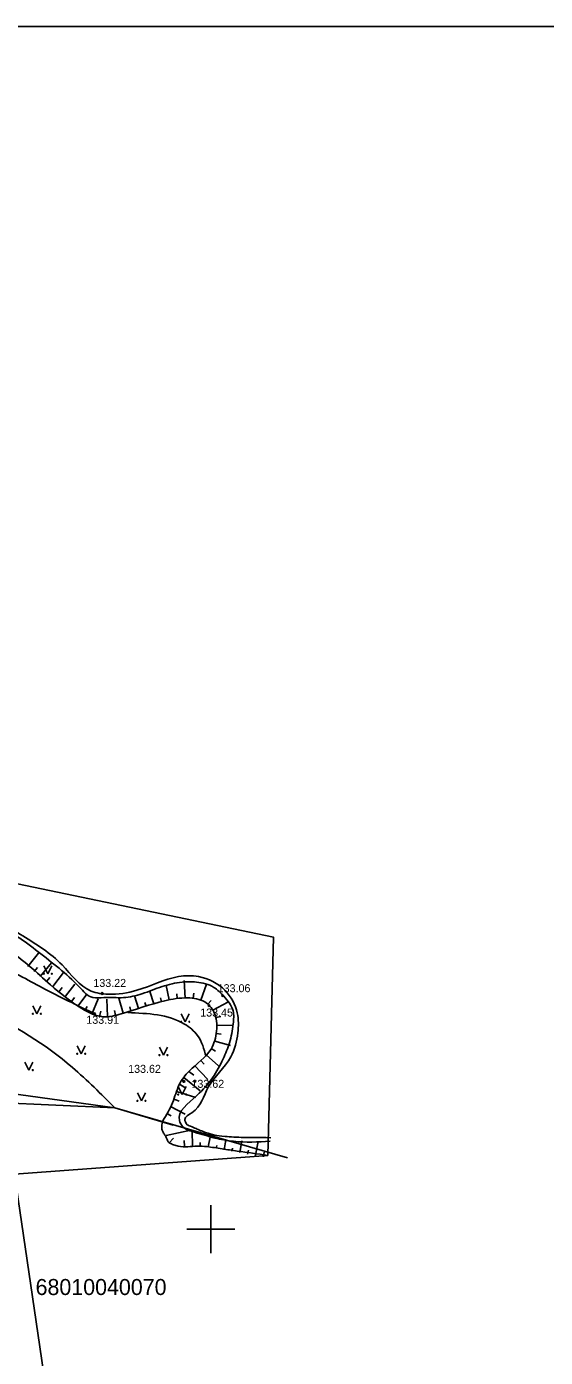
# Model space of a CAD drawing. Extents: x 728710 to 728960, y 272811 to 273475.
# Drawn here: x 728788.5 to 728820.9, y 273392 to 273475.1 of the extents above; entities that cross this region are included whole.
import ezdxf

# ---------------------------------------------------------------- set-up
doc = ezdxf.new("R2010")
doc.units = 0
for name, color, linetype in [('Level 10', 7, 'Continuous'), ('Level 12', 7, 'Continuous'), ('Level 28', 7, 'Continuous'), ('Level 30', 7, 'Continuous'), ('Level 31', 7, 'Continuous'), ('Level 33', 7, 'Continuous'), ('Level 34', 7, 'Continuous'), ('Level 48', 7, 'Continuous'), ('Level 57', 7, 'Continuous'), ('RAMI_PLAN_####_TKST_#', 7, 'Continuous'), ('RAMI_UZMR_####_####_#', 7, 'Continuous'), ('ROBZ_KADS_####_TKST_#', 7, 'Continuous'), ('ROBZ_UZMR_####_####_#', 7, 'Continuous'), ('TERT_KONT_####_####_#', 7, 'Continuous')]:
    doc.layers.add(name, color=color, linetype=linetype)

msp = doc.modelspace()

# ---------------------------------------------------------------- linework, layer by layer
at = {"layer": 'Level 10'}
for p, q in [((728800, 273401.5), (728800, 273400)), ((728798.5, 273400), (728800, 273400)), ((728800, 273400), (728800, 273398.5)), ((728800, 273400), (728801.5, 273400))]:
    msp.add_line(p, q, dxfattribs=at)
at = {"layer": 'Level 12'}
for p, q in [((728788.569, 273416.409), (728789.245, 273417.235)), ((728789.342, 273415.775), (728790.045, 273416.631)), ((728788.956, 273416.092), (728789.163, 273416.345)), ((728789.732, 273415.462), (728789.941, 273415.724)), ((728790.125, 273415.153), (728790.799, 273416.026)), ((728790.521, 273414.847), (728790.712, 273415.095)), ((728790.917, 273414.542), (728791.511, 273415.312)), ((728796.438, 273414.071), (728796.2, 273414.848)), ((728797.405, 273414.324), (728797.213, 273415.221)), ((728798.397, 273414.436), (728798.337, 273415.522)), ((728799.378, 273414.301), (728799.728, 273415.302)), ((728791.316, 273414.241), (728791.482, 273414.462)), ((728791.719, 273413.945), (728792.253, 273414.682)), ((728792.573, 273413.429), (728792.953, 273414.392)), ((728793.549, 273413.276), (728793.494, 273414.365)), ((728794.526, 273413.483), (728794.253, 273414.422)), ((728795.483, 273413.772), (728795.227, 273414.577)), ((728795.96, 273413.923), (728795.887, 273414.154)), ((728796.919, 273414.208), (728796.851, 273414.454)), ((728797.899, 273414.397), (728797.868, 273414.7)), ((728798.896, 273414.427), (728798.944, 273414.746)), ((728799.814, 273414.058), (728800.019, 273414.291)), ((728800.133, 273413.678), (728801.065, 273414.183)), ((728792.132, 273413.663), (728792.285, 273413.905)), ((728793.051, 273413.289), (728793.119, 273413.611)), ((728794.042, 273413.358), (728793.979, 273413.666)), ((728795.006, 273413.622), (728794.931, 273413.883)), ((728800.315, 273413.215), (728800.626, 273413.284)), ((728800.375, 273412.72), (728801.419, 273412.747)), ((728800.241, 273411.732), (728801.221, 273411.461)), ((728800.34, 273412.222), (728800.643, 273412.181)), ((728799.716, 273410.893), (728800.481, 273410.202)), ((728800.031, 273411.28), (728800.285, 273411.119)), ((728798.636, 273409.854), (728798.93, 273409.616)), ((728798.98, 273410.216), (728799.814, 273409.348)), ((728799.353, 273410.55), (728799.575, 273410.299)), ((728798.045, 273409.049), (728798.383, 273408.846)), ((728798.322, 273409.465), (728799.343, 273408.638)), ((728797.858, 273408.587), (728799.071, 273408.215)), ((728797.486, 273407.662), (728798.4, 273407.173)), ((728797.705, 273408.111), (728798.022, 273407.997)), ((728797.014, 273406.78), (728797.023, 273406.775)), ((728797.25, 273407.221), (728797.514, 273407.08)), ((728797.1, 273406.338), (728797.103, 273406.338)), ((728797.206, 273405.849), (728798.749, 273406.184)), ((728797.397, 273405.397), (728797.676, 273405.688)), ((728798.846, 273405.182), (728798.833, 273406.147)), ((728799.842, 273405.138), (728799.951, 273405.733)), ((728797.847, 273405.199), (728797.849, 273405.209)), ((728798.346, 273405.175), (728798.341, 273405.532)), ((728799.345, 273405.188), (728799.343, 273405.412)), ((728800.334, 273405.048), (728800.366, 273405.223)), ((728800.826, 273404.958), (728800.937, 273405.568)), ((728801.317, 273404.868), (728801.354, 273405.066)), ((728801.809, 273404.778), (728801.945, 273405.517)), ((728802.301, 273404.687), (728802.346, 273404.933)), ((728802.793, 273404.598), (728802.955, 273405.498)), ((728803.285, 273404.51), (728803.338, 273404.804))]:
    msp.add_line(p, q, dxfattribs=at)
for points in [[(728769.216, 273417.292), (728772.241, 273417.34), (728773.448, 273417.819), (728775.383, 273417.819), (728777.318, 273417.819), (728779.801, 273417.819), (728783.205, 273418.186), (728785.14, 273418.186), (728787.244, 273417.459), (728789.982, 273415.263), (728791.949, 273413.779), (728793.31, 273413.264), (728794.399, 273413.446), (728797.122, 273414.264), (728798.559, 273414.445), (728799.618, 273414.188), (728800.193, 273413.567), (728800.36, 273412.37), (728800.012, 273411.25), (728798.652, 273409.873), (728798.03, 273409.023), (728797.606, 273407.887), (728797.007, 273406.767)], [(728803.558, 273404.599), (728801.654, 273404.877), (728800.701, 273405.011), (728799.751, 273405.154), (728799.159, 273405.179), (728798.561, 273405.148), (728797.968, 273405.18), (728797.679, 273405.258), (728797.537, 273405.319), (728797.467, 273405.356), (728797.397, 273405.397), (728797.299, 273405.526), (728797.242, 273405.681), (728797.138, 273405.865), (728797.025, 273406.047), (728796.944, 273406.233), (728796.936, 273406.425), (728797.007, 273406.767)]]:
    msp.add_spline(points, degree=3, dxfattribs=at)
at = {"layer": 'Level 28'}
for p, q in [((728786.214, 273408.662), (728794.012, 273407.568)), ((728794.012, 273407.568), (728797.649, 273406.5))]:
    msp.add_line(p, q, dxfattribs=at)
at = {"layer": 'Level 30'}
for points in [[(728792.745, 273413.452), (728789.478, 273415.073), (728786.615, 273416.557), (728784.378, 273417.35), (728779.57, 273417.734)], [(728799.703, 273410.779), (728799.172, 273412.094), (728798.364, 273412.803), (728794.808, 273413.523)]]:
    msp.add_spline(points, degree=3, dxfattribs=at)
at = {"layer": 'Level 31'}
msp.add_spline([(728794.012, 273407.568), (728791.349, 273410.099), (728785.715, 273413.636), (728781.324, 273415.156)], degree=3, dxfattribs=at)
at = {"layer": 'Level 33'}
msp.add_spline([(728769.065, 273418.557), (728772.12, 273418.756), (728774.651, 273419.122), (728783.799, 273419.463), (728786.916, 273419.027), (728788.265, 273418.314), (728790.708, 273416.501), (728792.526, 273414.874), (728793.589, 273414.671), (728795.387, 273414.917), (728797.984, 273415.774), (728799.237, 273415.773), (728800.894, 273414.901), (728801.653, 273413.507), (728801.685, 273412.251), (728801.253, 273410.766), (728799.842, 273408.86), (728798.822, 273407.273), (728798.368, 273406.856), (728798.53, 273406.513)], degree=3, dxfattribs=at)
msp.add_open_spline([(728798.53, 273406.513), (728798.585, 273406.49), (728798.827, 273406.385), (728799.191, 273406.229), (728799.313, 273406.175), (728799.544, 273406.081), (728799.662, 273406.04), (728800.257, 273405.858), (728800.759, 273405.789), (728802.076, 273405.704), (728802.912, 273405.741), (728803.748, 273405.699)], degree=3, dxfattribs=at)
at = {"layer": 'Level 34'}
msp.add_spline([(728803.711, 273405.484), (728801.422, 273405.484), (728800.253, 273405.69), (728798.991, 273406.049), (728798.257, 273406.395), (728798.035, 273406.78), (728799.137, 273408.348), (728800.771, 273410.635), (728801.169, 273411.645), (728801.395, 273412.814), (728801.395, 273413.639), (728800.811, 273414.542), (728800.187, 273415.101), (728799.098, 273415.433), (728798.208, 273415.433), (728796.959, 273415.154), (728795.698, 273414.702), (728794.542, 273414.463), (728793.32, 273414.463), (728792.63, 273414.463), (728791.78, 273415.127), (728789.217, 273417.32), (728787.889, 273418.277), (728786.202, 273418.969), (728783.997, 273419.181), (728781.062, 273419.181), (728779.402, 273419.048), (728774.594, 273418.875), (728772.615, 273418.556), (728768.674, 273418.296), (728764.235, 273418.663), (728759.321, 273419.221), (728753.876, 273419.779), (728749.613, 273420.085), (728745.469, 273420.085), (728743.998, 273420.191)], degree=3, dxfattribs=at)
at = {"layer": 'Level 48'}
for centre in [(728793.211, 273414.718), (728799.885, 273413.957), (728800.74, 273414.587), (728792.745, 273413.452), (728798.316, 273409.225), (728799.003, 273409.238)]:
    msp.add_circle(centre, 0.0534, dxfattribs=at)
at = {"layer": 'RAMI_PLAN_####_TKST_#'}
msp.add_lwpolyline([(728728.89, 273202.048), (728728.89, 273475.126), (728912.915, 273475.126), (728912.915, 273202.048)], close=True, dxfattribs=at)
at = {"layer": 'RAMI_UZMR_####_####_#'}
msp.add_lwpolyline([(728810.773, 273260.978), (728802.611, 273315.901), (728795.796, 273348.362), (728794.274, 273357.438), (728805.771, 273362.009), (728805.234, 273373.998), (728803.936, 273379.727), (728791.234, 273379.578), (728787.734, 273403.429), (728803.558, 273404.599), (728803.908, 273418.239), (728787.419, 273421.679), (728754.475, 273424.404), (728743.982, 273420.563), (728745.23, 273392.888), (728745.879, 273378.489), (728747.149, 273361.103), (728773.116, 273356.557), (728775.22, 273317.659), (728767.872, 273315.668), (728768.286, 273308.258), (728775.846, 273306.093), (728776.746, 273299.712), (728774.767, 273288.109)], dxfattribs=at)
at = {"layer": 'ROBZ_UZMR_####_####_#'}
for p, q in [((728794.012, 273407.568), (728782.32, 273408.103)), ((728804.798, 273404.456), (728794.012, 273407.568))]:
    msp.add_line(p, q, dxfattribs=at)
at = {"layer": 'TERT_KONT_####_####_#'}
for p, q in [((728789.569, 273416.453), (728789.819, 273415.953)), ((728789.819, 273415.953), (728790.069, 273416.453)), ((728788.889, 273413.956), (728789.139, 273413.456)), ((728789.139, 273413.456), (728789.389, 273413.956)), ((728798.158, 273413.453), (728798.408, 273412.953)), ((728798.408, 273412.953), (728798.658, 273413.453)), ((728791.653, 273411.453), (728791.903, 273410.953)), ((728791.903, 273410.953), (728792.153, 273411.453)), ((728796.787, 273411.374), (728797.037, 273410.874)), ((728797.037, 273410.874), (728797.287, 273411.374)), ((728788.375, 273410.438), (728788.625, 273409.938)), ((728788.625, 273409.938), (728788.875, 273410.438)), ((728795.415, 273408.511), (728795.665, 273408.011)), ((728795.665, 273408.011), (728795.915, 273408.511)), ((728797.965, 273408.901), (728798.215, 273408.401)), ((728798.215, 273408.401), (728798.465, 273408.901))]:
    msp.add_line(p, q, dxfattribs=at)
for centre, radius in [((728789.568, 273415.953), 0.028), ((728790.068, 273415.953), 0.0263), ((728788.889, 273413.455), 0.028), ((728789.389, 273413.455), 0.0263), ((728798.158, 273412.952), 0.028), ((728798.658, 273412.952), 0.0263), ((728791.653, 273410.952), 0.028), ((728792.153, 273410.952), 0.0263), ((728796.787, 273410.874), 0.028), ((728797.287, 273410.874), 0.0263), ((728788.874, 273409.937), 0.0263), ((728797.964, 273408.401), 0.028), ((728798.464, 273408.401), 0.0263), ((728795.415, 273408.011), 0.028), ((728795.915, 273408.011), 0.0263)]:
    msp.add_circle(centre, radius, dxfattribs=at)

# ---------------------------------------------------------------- texts
at = {"layer": 'Level 57'}
for s, p in [(' 133.22', (728792.477, 273415.129)), (' 133.06', (728800.244, 273414.799)), (' 133.91', (728792.037, 273412.825)), (' 133.45', (728799.153, 273413.279)), (' 133.62', (728794.651, 273409.761)), (' 133.62', (728798.605, 273408.826))]:
    msp.add_text(s, height=0.5, dxfattribs=at).set_placement(p)
at = {"layer": 'ROBZ_KADS_####_TKST_#'}
msp.add_text('68010040070', height=1, dxfattribs=at).set_placement((728789.053, 273395.881))

doc.saveas('drawing.dxf')
